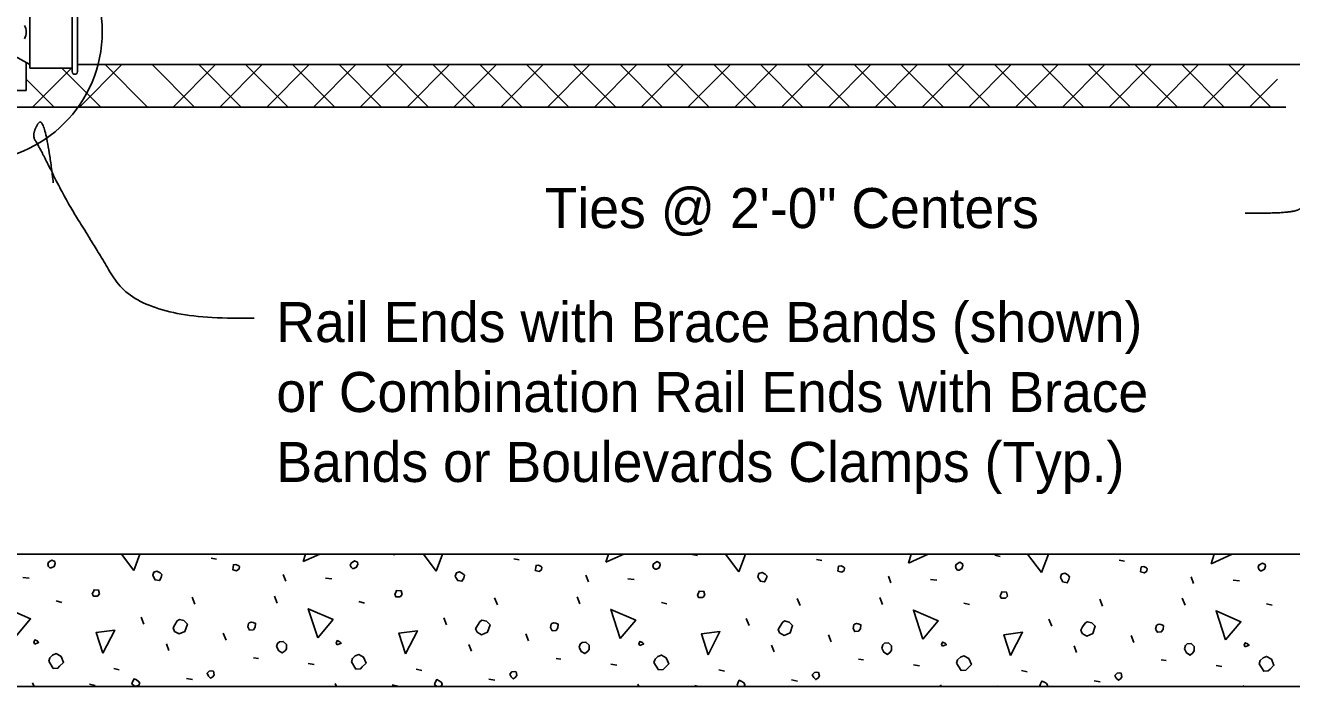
# Model space of a CAD drawing. Extents: x 110698 to 110915, y 110390 to 110472.
# Drawn here: x 110786.41 to 110792.78, y 110452.9 to 110456.22 of the extents above; entities that cross this region are included whole.
import ezdxf

# ---------------------------------------------------------------- set-up
doc = ezdxf.new("R2010")
doc.units = 0
for name, color, linetype in [('Border', 7, 'Continuous'), ('PlotBorder_dp', 7, 'Continuous'), ('SheetBorder_dp', 7, 'Continuous'), ('SheetLines_dp', 7, 'Continuous'), ('TextMisc', 7, 'Continuous')]:
    doc.layers.add(name, color=color, linetype=linetype)

msp = doc.modelspace()

# ---------------------------------------------------------------- linework, layer by layer
at = {"layer": 'PlotBorder_dp'}
msp.add_circle((110786.1422, 110456.193), 0.6527, dxfattribs=at)
for points in [[(110792.5505, 110455.2798), (110792.7733, 110455.2763), (110792.8582, 110455.3152), (110792.9891, 110455.4639), (110792.9042, 110455.7614), (110792.8618, 110456.0267)], [(110787.56, 110454.7515), (110786.9877, 110454.7336), (110786.7183, 110455.1744), (110786.6132, 110455.3423), (110786.4744, 110455.6197), (110786.438, 110455.6757), (110786.5063, 110455.786), (110786.5484, 110455.4318)]]:
    msp.add_open_spline(points, degree=2, dxfattribs=at)
at = {"layer": 'SheetBorder_dp'}
for p, q in [((110786.4443, 110455.8133), (110786.6433, 110456.0122)), ((110786.5912, 110456.0096), (110786.7875, 110455.8133)), ((110786.68, 110455.8133), (110786.8936, 110456.0268)), ((110786.8096, 110456.0268), (110787.0232, 110455.8133)), ((110787.0453, 110456.0268), (110787.2589, 110455.8133)), ((110787.1514, 110455.8133), (110787.365, 110456.0268)), ((110787.281, 110456.0268), (110787.4946, 110455.8133)), ((110787.3871, 110455.8133), (110787.6007, 110456.0268)), ((110787.5167, 110456.0268), (110787.7303, 110455.8133)), ((110787.6228, 110455.8133), (110787.8364, 110456.0268)), ((110787.7525, 110456.0268), (110787.966, 110455.8133)), ((110787.8585, 110455.8133), (110788.0721, 110456.0268)), ((110787.9882, 110456.0268), (110788.2017, 110455.8133)), ((110788.0942, 110455.8133), (110788.3078, 110456.0268)), ((110788.2239, 110456.0268), (110788.4374, 110455.8133)), ((110788.3299, 110455.8133), (110788.5435, 110456.0268)), ((110788.4596, 110456.0268), (110788.6731, 110455.8133)), ((110788.5656, 110455.8133), (110788.7792, 110456.0268)), ((110788.6953, 110456.0268), (110788.9088, 110455.8133)), ((110788.8013, 110455.8133), (110789.0149, 110456.0268)), ((110788.931, 110456.0268), (110789.1445, 110455.8133)), ((110789.0371, 110455.8133), (110789.2506, 110456.0268)), ((110789.1667, 110456.0268), (110789.3802, 110455.8133)), ((110789.2728, 110455.8133), (110789.4863, 110456.0268)), ((110789.4024, 110456.0268), (110789.6159, 110455.8133)), ((110789.5085, 110455.8133), (110789.722, 110456.0268)), ((110789.6381, 110456.0268), (110789.8516, 110455.8133)), ((110789.7442, 110455.8133), (110789.9577, 110456.0268)), ((110789.8738, 110456.0268), (110790.0873, 110455.8133)), ((110789.9799, 110455.8133), (110790.1934, 110456.0268)), ((110790.1095, 110456.0268), (110790.323, 110455.8133)), ((110790.2156, 110455.8133), (110790.4291, 110456.0268)), ((110790.3452, 110456.0268), (110790.5587, 110455.8133)), ((110790.4513, 110455.8133), (110790.6648, 110456.0268)), ((110790.5809, 110456.0268), (110790.7944, 110455.8133)), ((110790.687, 110455.8133), (110790.9005, 110456.0268)), ((110790.8166, 110456.0268), (110791.0301, 110455.8133)), ((110790.9227, 110455.8133), (110791.1362, 110456.0268)), ((110791.0523, 110456.0268), (110791.2658, 110455.8133)), ((110791.1584, 110455.8133), (110791.3719, 110456.0268)), ((110791.288, 110456.0268), (110791.5015, 110455.8133)), ((110791.3941, 110455.8133), (110791.6076, 110456.0268)), ((110791.5237, 110456.0268), (110791.7372, 110455.8133)), ((110791.6298, 110455.8133), (110791.8433, 110456.0268)), ((110791.7594, 110456.0268), (110791.9729, 110455.8133)), ((110791.8655, 110455.8133), (110792.079, 110456.0268)), ((110791.9951, 110456.0268), (110792.2086, 110455.8133)), ((110792.1012, 110455.8133), (110792.3147, 110456.0268)), ((110792.2308, 110456.0268), (110792.4443, 110455.8133)), ((110792.3369, 110455.8133), (110792.5504, 110456.0268)), ((110792.4665, 110456.0268), (110792.68, 110455.8133)), ((110786.4116, 110455.9534), (110786.5518, 110455.8133)), ((110792.5726, 110455.8133), (110792.7135, 110455.9542)), ((110786.7435, 110453.5632), (110786.7446, 110453.563)), ((110787.3439, 110453.5436), (110787.3704, 110453.5383)), ((110788.2497, 110453.5632), (110788.2684, 110453.5595)), ((110788.8677, 110453.54), (110788.8942, 110453.5347)), ((110789.7657, 110453.5613), (110789.7922, 110453.556)), ((110790.3915, 110453.5365), (110790.418, 110453.5312)), ((110791.2895, 110453.5577), (110791.3161, 110453.5524)), ((110791.9153, 110453.533), (110791.9418, 110453.5277)), ((110787.7187, 110453.4269), (110787.7063, 110453.4605)), ((110789.2425, 110453.4234), (110789.2301, 110453.457)), ((110786.3946, 110453.4464), (110786.4264, 110453.4428)), ((110787.9184, 110453.4428), (110787.9502, 110453.4393)), ((110789.4422, 110453.4393), (110789.474, 110453.4357)), ((110790.7663, 110453.4198), (110790.7539, 110453.4534)), ((110790.966, 110453.4357), (110790.9979, 110453.4322)), ((110792.2901, 110453.4163), (110792.2777, 110453.4499)), ((110792.4899, 110453.4322), (110792.5217, 110453.4287)), ((110786.5625, 110453.3279), (110786.5908, 110453.3208)), ((110787.2608, 110453.312), (110787.2467, 110453.3474)), ((110787.6762, 110453.3173), (110787.6621, 110453.3527)), ((110788.7846, 110453.3085), (110788.7705, 110453.3438)), ((110789.2, 110453.3138), (110789.1859, 110453.3491)), ((110790.3084, 110453.3049), (110790.2943, 110453.3403)), ((110790.7239, 110453.3102), (110790.7097, 110453.3456)), ((110791.8322, 110453.3014), (110791.8181, 110453.3368)), ((110792.2477, 110453.3067), (110792.2335, 110453.3421)), ((110788.0863, 110453.3244), (110788.1146, 110453.3173)), ((110789.6102, 110453.3208), (110789.6384, 110453.3138)), ((110791.134, 110453.3173), (110791.1623, 110453.3102)), ((110792.6578, 110453.3138), (110792.6861, 110453.3067)), ((110787.0045, 110453.2112), (110786.9903, 110453.2466)), ((110788.5283, 110453.2077), (110788.5141, 110453.2431)), ((110790.0521, 110453.2042), (110790.038, 110453.2395)), ((110791.5759, 110453.2006), (110791.5618, 110453.236)), ((110787.4181, 110453.1299), (110787.404, 110453.1653)), ((110788.9419, 110453.1264), (110788.9278, 110453.1617)), ((110790.4658, 110453.1229), (110790.4516, 110453.1582)), ((110791.9896, 110453.1193), (110791.9754, 110453.1547)), ((110787.13, 110453.0787), (110787.1176, 110453.1122)), ((110788.6538, 110453.0751), (110788.6414, 110453.1087)), ((110790.1776, 110453.0716), (110790.1652, 110453.1052)), ((110791.7014, 110453.0681), (110791.6891, 110453.1016)), ((110787.556, 110453.0415), (110787.5808, 110453.038)), ((110787.8318, 110453.0133), (110787.8618, 110453.0079)), ((110789.0798, 110453.038), (110789.1046, 110453.0345)), ((110789.3556, 110453.0097), (110789.3857, 110453.0044)), ((110790.6036, 110453.0345), (110790.6284, 110453.0309)), ((110792.1275, 110453.0309), (110792.1522, 110453.0274)), ((110786.8524, 110452.9885), (110786.8807, 110452.9814)), ((110788.3763, 110452.985), (110788.4045, 110452.9779)), ((110789.9001, 110452.9814), (110789.9284, 110452.9744)), ((110790.8794, 110453.0062), (110790.9095, 110453.0009)), ((110791.4239, 110452.9779), (110791.4522, 110452.9708)), ((110792.4032, 110453.0026), (110792.4333, 110452.9973)), ((110786.4513, 110452.8966), (110786.4441, 110452.916)), ((110786.7305, 110452.909), (110786.7588, 110452.9019)), ((110787.2184, 110452.9372), (110787.2484, 110452.9319)), ((110787.9738, 110452.8966), (110787.9679, 110452.9125)), ((110788.2543, 110452.9054), (110788.2826, 110452.8983)), ((110788.7422, 110452.9337), (110788.7722, 110452.9284)), ((110789.4963, 110452.8966), (110789.4917, 110452.909)), ((110789.7781, 110452.9019), (110789.7993, 110452.8966)), ((110790.266, 110452.9302), (110790.2961, 110452.9249)), ((110791.0188, 110452.8966), (110791.0155, 110452.9054)), ((110791.3019, 110452.8983), (110791.309, 110452.8966)), ((110791.7898, 110452.9266), (110791.8199, 110452.9213)), ((110792.5413, 110452.8966), (110792.5394, 110452.9019))]:
    msp.add_line(p, q, dxfattribs=at)
for points in [[(110786.5307, 110453.4941), (110786.5378, 110453.4941), (110786.5519, 110453.5012), (110786.5572, 110453.5171), (110786.5555, 110453.5259), (110786.5413, 110453.533), (110786.5236, 110453.5224), (110786.5201, 110453.5118), (110786.5236, 110453.5012), (110786.5307, 110453.4941)], [(110786.9532, 110453.4817), (110786.8912, 110453.5632)], [(110786.9837, 110453.5632), (110786.9532, 110453.4817)], [(110787.807, 110453.5259), (110787.8185, 110453.5632)], [(110787.8902, 110453.5632), (110787.807, 110453.5259)], [(110788.0545, 110453.4905), (110788.0616, 110453.4905), (110788.0757, 110453.4976), (110788.081, 110453.5135), (110788.0793, 110453.5224), (110788.0651, 110453.5294), (110788.0475, 110453.5188), (110788.0439, 110453.5082), (110788.0475, 110453.4976), (110788.0545, 110453.4905)], [(110788.477, 110453.4782), (110788.4124, 110453.5632)], [(110788.5088, 110453.5632), (110788.477, 110453.4782)], [(110789.3309, 110453.5224), (110789.3434, 110453.5632)], [(110789.4218, 110453.5632), (110789.3309, 110453.5224)], [(110789.5783, 110453.487), (110789.5854, 110453.487), (110789.5996, 110453.4941), (110789.6049, 110453.51), (110789.6031, 110453.5188), (110789.589, 110453.5259), (110789.5713, 110453.5153), (110789.5677, 110453.5047), (110789.5713, 110453.4941), (110789.5783, 110453.487)], [(110790.0008, 110453.4746), (110789.9335, 110453.5632)], [(110790.034, 110453.5632), (110790.0008, 110453.4746)], [(110790.8547, 110453.5188), (110790.8683, 110453.5632)], [(110790.9535, 110453.5632), (110790.8547, 110453.5188)], [(110791.1022, 110453.4835), (110791.1092, 110453.4835), (110791.1234, 110453.4905), (110791.1287, 110453.5065), (110791.1269, 110453.5153), (110791.1128, 110453.5224), (110791.0951, 110453.5118), (110791.0916, 110453.5012), (110791.0951, 110453.4905), (110791.1022, 110453.4835)], [(110791.5247, 110453.4711), (110791.4546, 110453.5632)], [(110791.5591, 110453.5632), (110791.5247, 110453.4711)], [(110792.3785, 110453.5153), (110792.3932, 110453.5632)], [(110792.4852, 110453.5632), (110792.3785, 110453.5153)], [(110792.626, 110453.4799), (110792.633, 110453.4799), (110792.6472, 110453.487), (110792.6525, 110453.5029), (110792.6507, 110453.5118), (110792.6366, 110453.5188), (110792.6189, 110453.5082), (110792.6154, 110453.4976), (110792.6189, 110453.487), (110792.626, 110453.4799)], [(110787.0522, 110453.4499), (110787.061, 110453.434), (110787.0823, 110453.4304), (110787.0911, 110453.4464), (110787.0946, 110453.4605), (110787.0858, 110453.4693), (110787.0699, 110453.4782), (110787.054, 110453.4729), (110787.0487, 110453.457), (110787.0522, 110453.4499)], [(110787.4517, 110453.4852), (110787.4712, 110453.4799), (110787.4835, 110453.4888), (110787.4853, 110453.5012), (110787.4818, 110453.5047), (110787.4676, 110453.5118), (110787.4553, 110453.51), (110787.4535, 110453.4976), (110787.4517, 110453.4852)], [(110788.576, 110453.4464), (110788.5849, 110453.4304), (110788.6061, 110453.4269), (110788.6149, 110453.4428), (110788.6184, 110453.457), (110788.6096, 110453.4658), (110788.5937, 110453.4746), (110788.5778, 110453.4693), (110788.5725, 110453.4534), (110788.576, 110453.4464)], [(110788.9755, 110453.4817), (110788.995, 110453.4764), (110789.0074, 110453.4852), (110789.0091, 110453.4976), (110789.0056, 110453.5012), (110788.9914, 110453.5082), (110788.9791, 110453.5065), (110788.9773, 110453.4941), (110788.9755, 110453.4817)], [(110790.0998, 110453.4428), (110790.1087, 110453.4269), (110790.1299, 110453.4234), (110790.1387, 110453.4393), (110790.1423, 110453.4534), (110790.1334, 110453.4623), (110790.1175, 110453.4711), (110790.1016, 110453.4658), (110790.0963, 110453.4499), (110790.0998, 110453.4428)], [(110790.4994, 110453.4782), (110790.5188, 110453.4729), (110790.5312, 110453.4817), (110790.5329, 110453.4941), (110790.5294, 110453.4976), (110790.5153, 110453.5047), (110790.5029, 110453.5029), (110790.5011, 110453.4905), (110790.4994, 110453.4782)], [(110791.6237, 110453.4393), (110791.6325, 110453.4234), (110791.6537, 110453.4198), (110791.6625, 110453.4357), (110791.6661, 110453.4499), (110791.6572, 110453.4587), (110791.6413, 110453.4676), (110791.6254, 110453.4623), (110791.6201, 110453.4464), (110791.6237, 110453.4393)], [(110792.0232, 110453.4746), (110792.0426, 110453.4693), (110792.055, 110453.4782), (110792.0568, 110453.4905), (110792.0532, 110453.4941), (110792.0391, 110453.5012), (110792.0267, 110453.4994), (110792.0249, 110453.487), (110792.0232, 110453.4746)], [(110786.7499, 110453.3527), (110786.7711, 110453.3527), (110786.7817, 110453.3633), (110786.7764, 110453.3827), (110786.7535, 110453.3845), (110786.7499, 110453.3739), (110786.7446, 110453.365), (110786.7499, 110453.3527), (110786.7464, 110453.3562)], [(110788.2737, 110453.3491), (110788.2949, 110453.3491), (110788.3056, 110453.3597), (110788.3002, 110453.3792), (110788.2773, 110453.3809), (110788.2737, 110453.3703), (110788.2684, 110453.3615), (110788.2737, 110453.3491), (110788.2702, 110453.3527)], [(110789.7975, 110453.3456), (110789.8188, 110453.3456), (110789.8294, 110453.3562), (110789.8241, 110453.3756), (110789.8011, 110453.3774), (110789.7975, 110453.3668), (110789.7922, 110453.358), (110789.7975, 110453.3456), (110789.794, 110453.3491)], [(110791.3214, 110453.3421), (110791.3426, 110453.3421), (110791.3532, 110453.3527), (110791.3479, 110453.3721), (110791.3249, 110453.3739), (110791.3214, 110453.3633), (110791.3161, 110453.3544), (110791.3214, 110453.3421), (110791.3178, 110453.3456)], [(110786.3557, 110453.1458), (110786.308, 110453.2926), (110786.4335, 110453.2378), (110786.3557, 110453.1458)], [(110787.8795, 110453.1423), (110787.8318, 110453.289), (110787.9573, 110453.2342), (110787.8795, 110453.1423)], [(110789.4033, 110453.1388), (110789.3556, 110453.2855), (110789.4811, 110453.2307), (110789.4033, 110453.1388)], [(110790.9272, 110453.1352), (110790.8794, 110453.282), (110791.0049, 110453.2272), (110790.9272, 110453.1352)], [(110792.451, 110453.1317), (110792.4032, 110453.2784), (110792.5287, 110453.2236), (110792.451, 110453.1317)], [(110787.1583, 110453.1741), (110787.1813, 110453.1617), (110787.2113, 110453.1741), (110787.2237, 110453.2112), (110787.206, 110453.2289), (110787.183, 110453.2342), (110787.1724, 110453.2272), (110787.16, 110453.2077), (110787.1512, 110453.1918), (110787.1583, 110453.1741)], [(110787.5277, 110453.1971), (110787.5366, 110453.1812), (110787.556, 110453.183), (110787.5649, 110453.1953), (110787.5666, 110453.2148), (110787.5543, 110453.2201), (110787.5454, 110453.2218), (110787.5348, 110453.2183), (110787.5313, 110453.2148), (110787.5277, 110453.1971)], [(110788.6821, 110453.1706), (110788.7051, 110453.1582), (110788.7351, 110453.1706), (110788.7475, 110453.2077), (110788.7298, 110453.2254), (110788.7068, 110453.2307), (110788.6962, 110453.2236), (110788.6839, 110453.2042), (110788.675, 110453.1883), (110788.6821, 110453.1706)], [(110789.0515, 110453.1936), (110789.0604, 110453.1777), (110789.0798, 110453.1794), (110789.0887, 110453.1918), (110789.0904, 110453.2112), (110789.0781, 110453.2165), (110789.0692, 110453.2183), (110789.0586, 110453.2148), (110789.0551, 110453.2112), (110789.0515, 110453.1936)], [(110790.2059, 110453.167), (110790.2289, 110453.1547), (110790.2589, 110453.167), (110790.2713, 110453.2042), (110790.2536, 110453.2218), (110790.2307, 110453.2272), (110790.22, 110453.2201), (110790.2077, 110453.2006), (110790.1988, 110453.1847), (110790.2059, 110453.167)], [(110790.5754, 110453.19), (110790.5842, 110453.1741), (110790.6036, 110453.1759), (110790.6125, 110453.1883), (110790.6143, 110453.2077), (110790.6019, 110453.213), (110790.593, 110453.2148), (110790.5824, 110453.2112), (110790.5789, 110453.2077), (110790.5754, 110453.19)], [(110791.7297, 110453.1635), (110791.7527, 110453.1511), (110791.7827, 110453.1635), (110791.7951, 110453.2006), (110791.7774, 110453.2183), (110791.7545, 110453.2236), (110791.7439, 110453.2165), (110791.7315, 110453.1971), (110791.7226, 110453.1812), (110791.7297, 110453.1635)], [(110792.0992, 110453.1865), (110792.108, 110453.1706), (110792.1275, 110453.1723), (110792.1363, 110453.1847), (110792.1381, 110453.2042), (110792.1257, 110453.2095), (110792.1169, 110453.2112), (110792.1063, 110453.2077), (110792.1027, 110453.2042), (110792.0992, 110453.1865)], [(110786.7976, 110453.0645), (110786.7641, 110453.1688), (110786.8578, 110453.1812), (110786.7976, 110453.0645)], [(110788.3215, 110453.061), (110788.2879, 110453.1653), (110788.3816, 110453.1777), (110788.3215, 110453.061)], [(110789.8453, 110453.0574), (110789.8117, 110453.1617), (110789.9054, 110453.1741), (110789.8453, 110453.0574)], [(110791.3691, 110453.0539), (110791.3355, 110453.1582), (110791.4292, 110453.1706), (110791.3691, 110453.0539)], [(110786.4547, 110453.1105), (110786.4741, 110453.1193), (110786.4671, 110453.1264), (110786.4547, 110453.1317), (110786.4494, 110453.1193), (110786.4547, 110453.1105)], [(110787.6727, 110453.0981), (110787.6833, 110453.0769), (110787.701, 110453.0663), (110787.7151, 110453.0769), (110787.7222, 110453.0875), (110787.7222, 110453.1087), (110787.7063, 110453.1246), (110787.6868, 110453.1229), (110787.678, 110453.114), (110787.6727, 110453.0981)], [(110787.9785, 110453.1069), (110787.998, 110453.1158), (110787.9909, 110453.1229), (110787.9785, 110453.1282), (110787.9732, 110453.1158), (110787.9785, 110453.1069)], [(110789.1965, 110453.0946), (110789.2071, 110453.0734), (110789.2248, 110453.0627), (110789.2389, 110453.0734), (110789.246, 110453.084), (110789.246, 110453.1052), (110789.2301, 110453.1211), (110789.2106, 110453.1193), (110789.2018, 110453.1105), (110789.1965, 110453.0946)], [(110789.5023, 110453.1034), (110789.5218, 110453.1122), (110789.5147, 110453.1193), (110789.5023, 110453.1246), (110789.497, 110453.1122), (110789.5023, 110453.1034)], [(110790.7203, 110453.091), (110790.7309, 110453.0698), (110790.7486, 110453.0592), (110790.7627, 110453.0698), (110790.7698, 110453.0804), (110790.7698, 110453.1016), (110790.7539, 110453.1175), (110790.7345, 110453.1158), (110790.7256, 110453.1069), (110790.7203, 110453.091)], [(110791.0261, 110453.0999), (110791.0456, 110453.1087), (110791.0385, 110453.1158), (110791.0261, 110453.1211), (110791.0208, 110453.1087), (110791.0261, 110453.0999)], [(110792.2441, 110453.0875), (110792.2547, 110453.0663), (110792.2724, 110453.0557), (110792.2866, 110453.0663), (110792.2936, 110453.0769), (110792.2936, 110453.0981), (110792.2777, 110453.114), (110792.2583, 110453.1122), (110792.2494, 110453.1034), (110792.2441, 110453.0875)], [(110792.55, 110453.0963), (110792.5694, 110453.1052), (110792.5623, 110453.1122), (110792.55, 110453.1175), (110792.5447, 110453.1052), (110792.55, 110453.0963)], [(110786.5254, 110453.0256), (110786.5484, 110452.9885), (110786.5714, 110452.9903), (110786.5802, 110452.9991), (110786.5997, 110453.0186), (110786.5873, 110453.0486), (110786.5625, 110453.0627), (110786.5449, 110453.0557), (110786.5307, 110453.0415), (110786.5254, 110453.0256)], [(110788.0492, 110453.0221), (110788.0722, 110452.985), (110788.0952, 110452.9867), (110788.104, 110452.9956), (110788.1235, 110453.015), (110788.1111, 110453.0451), (110788.0863, 110453.0592), (110788.0687, 110453.0521), (110788.0545, 110453.038), (110788.0492, 110453.0221)], [(110789.573, 110453.0186), (110789.596, 110452.9814), (110789.619, 110452.9832), (110789.6278, 110452.992), (110789.6473, 110453.0115), (110789.6349, 110453.0415), (110789.6102, 110453.0557), (110789.5925, 110453.0486), (110789.5783, 110453.0345), (110789.573, 110453.0186)], [(110791.0969, 110453.015), (110791.1198, 110452.9779), (110791.1428, 110452.9797), (110791.1517, 110452.9885), (110791.1711, 110453.0079), (110791.1587, 110453.038), (110791.134, 110453.0521), (110791.1163, 110453.0451), (110791.1022, 110453.0309), (110791.0969, 110453.015)], [(110792.6207, 110453.0115), (110792.6437, 110452.9744), (110792.6666, 110452.9761), (110792.6755, 110452.985), (110792.6949, 110453.0044), (110792.6825, 110453.0345), (110792.6578, 110453.0486), (110792.6401, 110453.0415), (110792.626, 110453.0274), (110792.6207, 110453.0115)], [(110787.3297, 110452.9496), (110787.3404, 110452.939), (110787.351, 110452.9461), (110787.358, 110452.9567), (110787.3545, 110452.9744), (110787.3457, 110452.9761), (110787.3333, 110452.9744), (110787.3227, 110452.9638), (110787.3297, 110452.9496)], [(110788.8536, 110452.9461), (110788.8642, 110452.9355), (110788.8748, 110452.9425), (110788.8818, 110452.9531), (110788.8783, 110452.9708), (110788.8695, 110452.9726), (110788.8571, 110452.9708), (110788.8465, 110452.9602), (110788.8536, 110452.9461)], [(110790.3774, 110452.9425), (110790.388, 110452.9319), (110790.3986, 110452.939), (110790.4057, 110452.9496), (110790.4021, 110452.9673), (110790.3933, 110452.9691), (110790.3809, 110452.9673), (110790.3703, 110452.9567), (110790.3774, 110452.9425)], [(110791.9012, 110452.939), (110791.9118, 110452.9284), (110791.9224, 110452.9355), (110791.9295, 110452.9461), (110791.9259, 110452.9638), (110791.9171, 110452.9655), (110791.9047, 110452.9638), (110791.8941, 110452.9531), (110791.9012, 110452.939)], [(110786.955, 110452.9001), (110786.9674, 110452.8983), (110786.9797, 110452.9036), (110786.9833, 110452.9143), (110786.978, 110452.9231), (110786.9674, 110452.9302), (110786.955, 110452.9355), (110786.9479, 110452.9213), (110786.9444, 110452.9107), (110786.955, 110452.9001)], [(110788.4953, 110452.8966), (110788.5035, 110452.9001), (110788.5071, 110452.9107), (110788.5018, 110452.9196), (110788.4912, 110452.9266), (110788.4788, 110452.9319), (110788.4717, 110452.9178), (110788.4682, 110452.9072), (110788.4788, 110452.8966)], [(110790.0274, 110452.8966), (110790.0309, 110452.9072), (110790.0256, 110452.916), (110790.015, 110452.9231), (110790.0026, 110452.9284), (110789.9955, 110452.9143), (110789.992, 110452.9036), (110789.9991, 110452.8966)], [(110791.5524, 110452.8966), (110791.5547, 110452.9036), (110791.5494, 110452.9125), (110791.5388, 110452.9196), (110791.5264, 110452.9249), (110791.5194, 110452.9107), (110791.5158, 110452.9001), (110791.5194, 110452.8966)]]:
    msp.add_lwpolyline(points, dxfattribs=at)
at = {"layer": 'SheetLines_dp'}
for p, q in [((110779.5973, 110455.8133), (110792.755, 110455.8133)), ((110774.7539, 110453.5632), (110797.5277, 110453.5632)), ((110774.7539, 110452.8966), (110797.5277, 110452.8966))]:
    msp.add_line(p, q, dxfattribs=at)
at = {"layer": 'TextMisc'}
for p, q in [((110786.4303, 110456.2818), (110786.4303, 110456.0096)), ((110786.6433, 110456.3014), (110786.6433, 110455.9917)), ((110786.6701, 110456.3014), (110786.6701, 110455.9917)), ((110786.4303, 110456.0277), (110786.2164, 110456.1463)), ((110786.4116, 110455.8966), (110786.4116, 110456.038)), ((110786.6433, 110456.0096), (110786.4303, 110456.0096)), ((110795.6114, 110456.0268), (110786.6701, 110456.0268)), ((110786.3491, 110455.8966), (110786.4116, 110455.8966))]:
    msp.add_line(p, q, dxfattribs=at)
msp.add_arc((110786.6566, 110455.9915), 0.0134, 180, 0, dxfattribs=at)
msp.add_ellipse((110786.334, 110456.1905), major_axis=(0.0776, 0), ratio=0.957868, start_param=5.810211, end_param=6.75616, dxfattribs=at)

# ---------------------------------------------------------------- texts
at = {"layer": 'Border'}
msp.add_text('Ties @ 2\'-0" Centers', height=0.2016, dxfattribs=at).set_placement((110789.0227, 110455.2041))
at = {"layer": 'PlotBorder_dp'}
for s, p in [('Rail Ends with Brace Bands (shown)', (110787.6716, 110454.6305)), ('or Combination Rail Ends with Brace', (110787.6716, 110454.2785)), ('Bands or Boulevards Clamps (Typ.)', (110787.6716, 110453.9265))]:
    msp.add_text(s, height=0.2016, dxfattribs=at).set_placement(p)

doc.saveas('drawing.dxf')
